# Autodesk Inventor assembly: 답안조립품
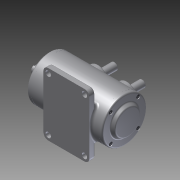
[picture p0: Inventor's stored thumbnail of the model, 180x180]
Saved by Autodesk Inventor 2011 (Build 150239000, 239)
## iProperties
Created: 2014-12
Part Number: 답안조립품
Document SubType Name: Assembly
Designer: user
Author: user
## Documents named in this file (10)
- D:\441225V1009\답안조립품.iam
- D:\441225V1009\2.본체.ipt
- D:\441225V1009\앞커버.ipt
- D:\441225V1009\뒷커버.ipt
- D:\441225V1009\3. 축.ipt
- D:\441225V1009\베어링 6203.ipt
- D:\441225V1009\오일실.ipt
- D:\441225V1009\부시.ipt
- D:\441225V1009\슬라이더.ipt
- D:\441225V1009\M4-소켓머리.ipt
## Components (13 placed, 5 different names)
1. 2.본체:1 — 각도:1
2. 3. 축:1 — 각도:1
3. 7-베어링 6203:1
4. 8-오일실:1
5. 7-베어링 6203:2
6. 9-M4-소켓머리:1
7. 9-M4-소켓머리:2
8. 9-M4-소켓머리:3
9. 9-M4-소켓머리:4
10. 9-M4-소켓머리:5
11. 9-M4-소켓머리:6
12. 9-M4-소켓머리:7
13. 9-M4-소켓머리:8
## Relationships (1: Angle 1)
- 각도:1 [Angle]: 2.본체:1 ↔ 3. 축:1
